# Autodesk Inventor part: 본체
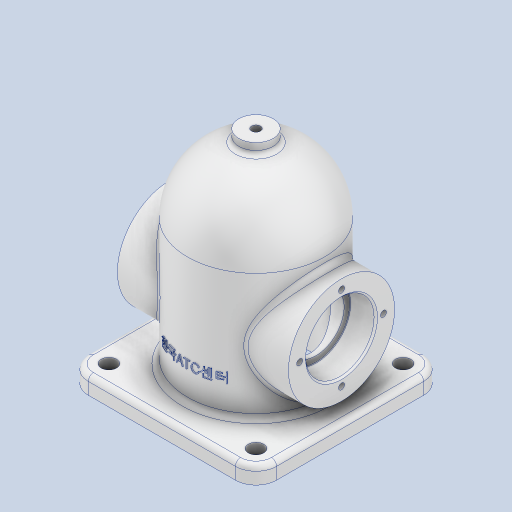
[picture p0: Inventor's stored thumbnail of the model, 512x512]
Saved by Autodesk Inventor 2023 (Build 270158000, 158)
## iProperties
Created: 2025-04
Part Number: 본체
Material: 알루미늄 6061
Document SubType Name: Modeling
Designer: Admin
Density: 2.7 g/cm^3
Appearance: 알루미늄 - 평지
Mass: 866.007 g
Surface Area: 800.421 cm^2
Volume: 320.743 cm^3
Author: Admin
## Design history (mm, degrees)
sketch "스케치1"
  geometry: L1 (-56, 0)-(56, 0) reference; L2 (0, -59.8)-(0, 99.8) reference; L3 (-40, -37)-(40, -37); L4 (40, -37)-(40, 37); L5 (40, 37)-(-40, 37); L6 (-40, 37)-(-40, -37); L7 (-40, -37)-(40, 37); L8 (40, -37)-(-40, 37); A1 r 40 centre (0, 37) between (40, 37) and (-40, 37); 3 further points
  constraints: 12 end point, 3 midpoint, 2 parallel, 2 point on circle, 1 centre point, 1 horizontal, 1 perpendicular
  dimensions: "d4" = 74 distance between parallel lines of L3 L5; "d27" = 40 radius of A1
revolve "회전1" sketch "스케치1" stored, may be unused: angle "d6" = 90 deg
sketch "스케치2"
  geometry: L1 (-55, 55)-(55, 55); L2 (55, 55)-(55, -55); L3 (55, -55)-(-55, -55); L4 (-55, -55)-(-55, 55); L5 (-55, 55)-(55, -55); L6 (55, 55)-(-55, -55); 1 further point
  constraints: 12 end point, 2 midpoint, 2 parallel, 1 horizontal, 1 perpendicular
  dimensions: "d7" = 110 distance of L1.end L2.end; "d8" = 110 distance of L2.end L3.end
extrude "돌출1" join sketch "스케치2" distance "d9" = 10; taper "d10" = 0 deg
sketch "스케치3"
  geometry: L1 (-62.6, 0)-(46.6, 0) reference; L2 (0, -77)-(0, 77) reference; L3 (1, 53.337)-(1, -53.714); L4 (-47, -55)-(-47, 55) reference; C1 r 31 at (0, 0); 1 further point
  constraints: 2 end point, 1 centre point, 1 coincident, 1 vertical
  dimensions: "d11" = 48 distance between parallel lines of L3 L4; "d12" = 62 diameter of C1
extrude "돌출2" join sketch "스케치3" stored distance "d13" = 100; taper "d14" = 0 deg
sketch "스케치4"
  geometry: C1 r 10 at (0, 0); 1 further point
  constraints: 1 centre point, 1 coincident
  dimensions: "d15" = 20 diameter of C1
extrude "돌출3" join sketch "스케치4" distance "d16" = 82; taper "d17" = 0 deg
sketch "스케치5"
  geometry: L1 (30.551, 1)-(-29.029, 1); L2 (55, -47)-(-55, -47) reference; L3 (0, -71.8)-(0, 101.8) reference; C1 r 16.5 at (0, 1); C2 r 20 at (0, 1); 1 further point
  constraints: 2 centre point, 2 end point, 2 point on line, 1 coincident, 1 horizontal
  dimensions: "d66" = 48 distance between parallel lines of L1 L2; "d67" = 33 diameter of C1; "d68" = 40 diameter of C2
sketch "스케치6"
  geometry: L1 (0, -72.8)-(0, 107.8) reference; L2 (-51.735, 1)-(51.369, 1); L3 (55, -47)-(-55, -47) reference; C1 r 20 at (0, 1); C2 r 16.5 at (0, 1); 1 further point
  constraints: 2 centre point, 2 end point, 2 point on line, 1 coincident, 1 horizontal
  dimensions: "d69" = 48 distance between parallel lines of L2 L3; "d70" = 40 diameter of C1; "d71" = 33 diameter of C2
extrude "돌출6" cut sketch "스케치6" stored distance "d25" = 15; taper "d26" = 0 deg
sketch "스케치7" dims "d28" = 32
  geometry: L1 (40, -37)-(-40, -37) reference; L2 (-32, 37)-(32, 37); L3 (32, 37)-(32, -37); L4 (32, -37)-(-32, -37); L5 (-32, -37)-(-32, 37); L6 (-32, 37)-(32, -37); L7 (32, 37)-(-32, -37); L8 (-77, 0)-(77, 0) reference; L9 (0, -72.8)-(0, 107.8) reference; 4 further points
  constraints: 12 end point, 3 midpoint, 2 parallel, 1 horizontal, 1 perpendicular, 1 point on line, 3 other
revolve "회전2" sketch "스케치7" stored, may be unused: angle "d29" = 90 deg
sketch "스케치8"
  geometry: C1 r 32 at (0, 0); 1 further point
  constraints: 1 centre point, 1 coincident
  dimensions: "d30" = 32 radius of C1
extrude "돌출7" cut sketch "스케치8" distance "d31" = 15; taper "d32" = 0 deg
sketch "스케치9"
  geometry: L1 (0, -71.8)-(0, 101.8) reference; L2 (-77, 0)-(77, 0) reference; 2 further points
  constraints: 1 point on line
  dimensions: "d33" = 51 diameter of point (0, 25.5) L2
hole "구멍1" sketch "스케치9" at (0, 25.5) diameter "d34" = 3.45873; stored, may be unused: countersink angle "d38" = 90 deg, drill point angle "d40" = 118 deg; dims "d35" = 8, "d36" = 8, "d37" = 10, "d39" = 10.8
sketch "스케치10"
  geometry: 2 further points
  constraints: 1 coincident
hole "구멍2" sketch "스케치10" at (0, 0) diameter "d44" = 5.1881; stored, may be unused: countersink angle "d48" = 90 deg, drill point angle "d50" = 118 deg; dims "d45" = 20, "d46" = 4, "d47" = 2, "d49" = 16
fillet "모깎기1" dims "d51" = 12
sketch "스케치11"
  geometry: L1 (-77, 0)-(77, 0) reference; L2 (0, 77)-(0, -77) reference; C1 r 4.5 at (-43, 43); C2 r 4.5 at (43, 43); C3 r 4.5 at (-43, -43); C4 r 4.5 at (43, -43); A1 r 12 centre (-43, 43) between (-43, 55) and (-55, 43) reference; 1 further point
  constraints: 4 centre point, 3 symmetric about line, 1 concentric, 3 other
  dimensions: "d52" = 9 diameter of C1
extrude "돌출8" cut sketch "스케치11" stored distance "d53" = 15; taper "d54" = 0 deg
fillet "모깎기2" dims "d55" = 3
node "작업 평면1"
sketch "스케치13"
  geometry: L1 (-77, 0)-(77, 0) reference; L2 (0, -72.8)-(0, 107.8) reference; L3 (43, -47)-(-43, -47) reference; 2 further points
  constraints: 1 point on line, 1 other
  dimensions: "d63" = 30 distance from line of L3 point (0, -17)
feature "엠보싱2" sketch "스케치13" dims "d64" = 0.5, "d65" = 0
extrude "돌출9" cut sketch "스케치6" distance "d72" = 15; taper "d73" = 0 deg
extrude "돌출10" cut sketch "스케치5" distance "d74" = 15; taper "d75" = 0 deg
chamfer "모따기2" distance "d79" = 1; stored, may be unused: second distance "d80" = 2, angle "d81" = 45 deg
fillet "모깎기4" dims "d82" = 0.3
fillet "모깎기5" dims "d83" = 0.3
feature "ɸ耀ɺ耀ɼ耀ɾ耀ʀ耀ʂ耀ʄ耀ʆ耀" dims "d4" = 74, "d6" = 90 deg, "d7" = 110, "d8" = 110, "d9" = 10, "d10" = 0, "d11" = 48, "d12" = 62, "d13" = 100, "d14" = 0, "d15" = 20, "d16" = 82, "d17" = 0, "d25" = 15, "d26" = 0, "d27" = 40, "d28" = 32, "d29" = 90 deg, "d30" = 32, "d31" = 15, "d32" = 0, "d33" = 51, "d34" = 3.45873, "d35" = 8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
node "솔리드1"
mirror "미러1"
pattern_circular "원형 패턴2" dims angle "d77" = 360 deg
mirror "미러2"
feature "A9D066F2-1C7D-4E18-AEED-F7BC21143FA4" dims "d34" = 3.45873, "d35" = 8, "d36" = 8, "d37" = 10, "d38" = 90 deg, "d39" = 10.8, "d40" = 118 deg
